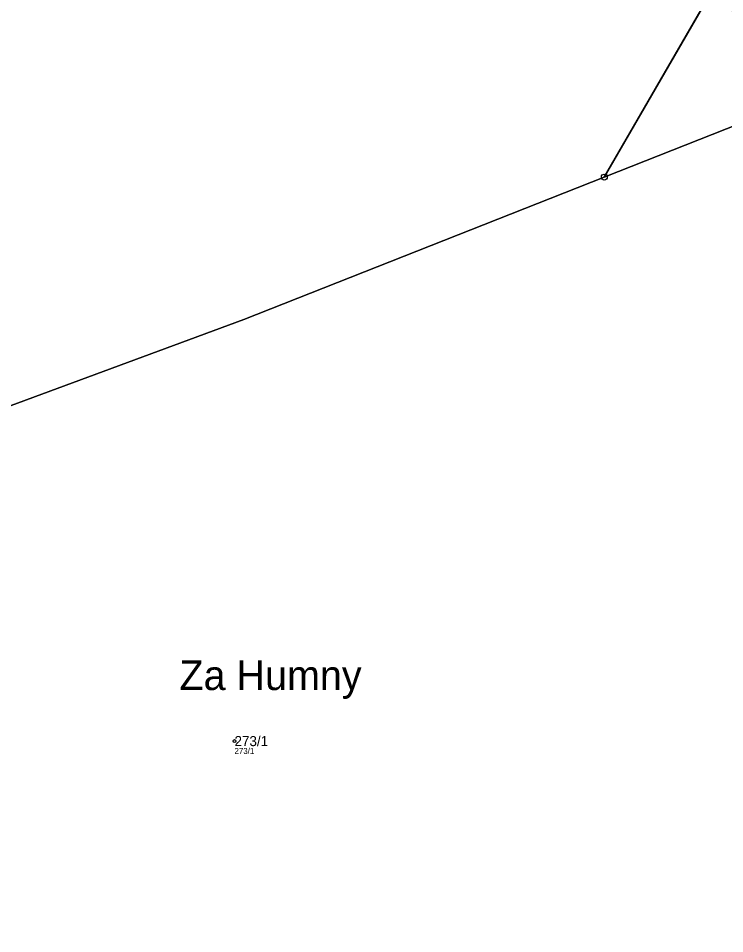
# Model space of a CAD drawing. Extents: x -734504 to -730695, y -1027923 to -1024502.
# Drawn here: x -732350.8 to -732231.2, y -1026240.6 to -1026085.7 of the extents above; entities that cross this region are included whole.
import ezdxf

# ---------------------------------------------------------------- set-up
doc = ezdxf.new("R2010")
doc.units = 0
for name, color, linetype in [('Definiční body', 7, 'Continuous'), ('Hranice parcel', 7, 'Continuous'), ('Parcelní čísla', 7, 'Continuous'), ('Polygon parcely', 7, 'Continuous'), ('Pop  PČ popisy', 7, 'Continuous'), ('Značky bodu BP', 7, 'Continuous')]:
    doc.layers.add(name, color=color, linetype=linetype)

msp = doc.modelspace()

# ---------------------------------------------------------------- linework, layer by layer
at = {"layer": 'Definiční body'}
msp.add_circle((-732314.22, -1026208.05), 0.25, dxfattribs=at)
at = {"layer": 'Hranice parcel'}
msp.add_line((-732251.61, -1026112.61), (-732233.98, -1026082.13), dxfattribs=at)
for points in [[(-732146.93, -1026164.06), (-732148.79, -1026155.14), (-732212.63, -1026097.21), (-732251.61, -1026112.61)], [(-732251.61, -1026112.61), (-732312.64, -1026136.72), (-732397.15, -1026167.88)]]:
    msp.add_lwpolyline(points, dxfattribs=at)
at = {"layer": 'Polygon parcely'}
for points in [[(-732251.61, -1026112.61), (-732233.98, -1026082.13), (-732236.41, -1026080.73), (-732283.88, -1026051.13), (-732307.25, -1026036.07), (-732334.7, -1026015.44), (-732368.89, -1025987.51), (-732379.43, -1025981), (-732402.19, -1026003.86), (-732427.49, -1026028.82), (-732441.52, -1026042.86), (-732459.96, -1026061.26), (-732447.58, -1026082.01), (-732445.42, -1026085.63), (-732435.2, -1026102.95), (-732424.99, -1026120.24), (-732423.81, -1026122.33), (-732421.25, -1026126.85), (-732420.04, -1026128.72), (-732409.85, -1026146.12), (-732397.15, -1026167.88), (-732312.64, -1026136.72)], [(-732146.93, -1026164.06), (-732134.81, -1026153.42), (-732138.99, -1026144.39), (-732152.08, -1026135.35), (-732210.73, -1026095.55), (-732233.98, -1026082.13), (-732251.61, -1026112.61), (-732212.63, -1026097.21), (-732148.79, -1026155.14)]]:
    msp.add_lwpolyline(points, close=True, dxfattribs=at)
msp.add_lwpolyline([(-732192.04, -1026255.29), (-732180.05, -1026229.9), (-732166.07, -1026198.43), (-732155.08, -1026176.13), (-732146.93, -1026164.06), (-732148.79, -1026155.14), (-732212.63, -1026097.21), (-732251.61, -1026112.61), (-732312.64, -1026136.72), (-732397.15, -1026167.88), (-732417.67, -1026174.36), (-732433.5, -1026184.3), (-732435.18, -1026185.39), (-732440.86, -1026187.64), (-732442.7, -1026188.68), (-732460.7, -1026199.22), (-732469.38, -1026204.38), (-732481.1, -1026211.23), (-732483.23, -1026212.65), (-732470.37, -1026233.19), (-732440.69, -1026280.59)], dxfattribs=at)
at = {"layer": 'Značky bodu BP'}
for radius in [0.5, 0.0303]:
    msp.add_circle((-732251.61, -1026112.61), radius, dxfattribs=at)

# ---------------------------------------------------------------- texts
at = {"layer": 'Definiční body'}
msp.add_text('273/1', height=1, dxfattribs=at).set_placement((-732314.22, -1026210.21))
at = {"layer": 'Parcelní čísla'}
msp.add_text('273/1', height=1.7, dxfattribs=at).set_placement((-732314.22, -1026208.9))
at = {"layer": 'Pop  PČ popisy'}
msp.add_text('Za Humny', height=5, dxfattribs=at).set_placement((-732323.54, -1026199.41))

doc.saveas('drawing.dxf')
